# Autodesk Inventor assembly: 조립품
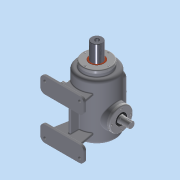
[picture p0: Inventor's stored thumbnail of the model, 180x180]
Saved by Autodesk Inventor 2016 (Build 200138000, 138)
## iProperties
Created: 2018-11
Part Number: 조립품
Material: 일반
Document SubType Name: Assembly
Designer: 공506_41
Author: 공506_41
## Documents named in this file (15)
- C:\Users\공506_41\Desktop\새 폴더 (2)\381121V1006\조립품.iam
- C:\Users\공506_41\Desktop\새 폴더 (2)\381121V1006\가변스프링.ipt
- C:\Users\공506_41\Desktop\새 폴더 (2)\381121V1006\베어링 6205.ipt
- 베어링 6205.ipt
- C:\Users\공506_41\Desktop\새 폴더 (2)\381121V1006\본체.ipt
- C:\Users\공506_41\Desktop\새 폴더 (2)\381121V1006\볼트 M4x0.7.ipt
- C:\Users\공506_41\Desktop\새 폴더 (2)\381121V1006\부시.ipt
- C:\Users\공506_41\Desktop\새 폴더 (2)\381121V1006\상부커버.ipt
- C:\Users\공506_41\Desktop\새 폴더 (2)\381121V1006\슬라이드 커버.ipt
- C:\Users\공506_41\Desktop\새 폴더 (2)\381121V1006\슬라이드.ipt
- C:\Users\공506_41\Desktop\새 폴더 (2)\381121V1006\오일실.ipt
- 오일실.ipt
- C:\Users\공506_41\Desktop\새 폴더 (2)\381121V1006\육각머리볼트 M4.ipt
- C:\Users\공506_41\Desktop\새 폴더 (2)\381121V1006\축 커버.ipt
- C:\Users\공506_41\Desktop\새 폴더 (2)\381121V1006\편심축.ipt
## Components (13 placed, 2 different names)
1. 가변스프링:1
2. M4x0.7:2
3. M4x0.7:4
4. M4x0.7:5
5. M4x0.7:6
6. M4x0.7:1
7. M4x0.7:7
8. M4x0.7:8
9. M4x0.7:9
10. M4x0.7:3
11. M4x0.7:10
12. M4x0.7:11
13. M4x0.7:12
